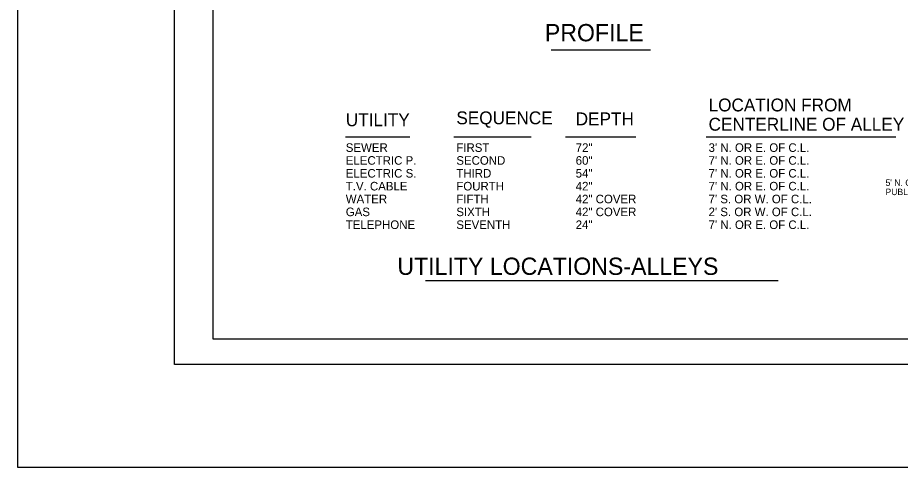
# Model space of a CAD drawing. Extents: x 524397 to 525117, y 3701341 to 3701821.
# Drawn here: x 524396.8 to 524603, y 3701341 to 3701445.9 of the extents above; entities that cross this region are included whole.
import ezdxf

# ---------------------------------------------------------------- set-up
doc = ezdxf.new("R2010")
doc.units = 0
for name, color, linetype in [('Level 1', 7, 'Continuous'), ('Level 9', 7, 'Continuous'), ('Pam batch print border', 7, 'Continuous')]:
    doc.layers.add(name, color=color, linetype=linetype)

msp = doc.modelspace()

# ---------------------------------------------------------------- linework, layer by layer
at = {"layer": 'Level 1'}
for p, q in [((524442.4, 3701790.98), (524442.4, 3701370.98)), ((524521.38, 3701438.43), (524544.58, 3701438.43)), ((524473.35, 3701418.16), (524488.42, 3701418.16)), ((524498.7, 3701418.16), (524516.74, 3701418.16)), ((524524.74, 3701418.16), (524541.18, 3701418.16)), ((524557.63, 3701418.16), (524601.94, 3701418.16)), ((524492.06, 3701384.56), (524574.43, 3701384.56)), ((524442.4, 3701370.98), (525097.4, 3701370.98))]:
    msp.add_line(p, q, dxfattribs=at)
at = {"layer": 'Level 9'}
msp.add_lwpolyline([(524396.79, 3701820.98), (525116.79, 3701820.98), (525116.79, 3701340.98), (524396.79, 3701340.98)], close=True, dxfattribs=at)
at = {"layer": 'Pam batch print border'}
msp.add_lwpolyline([(524433.4, 3701796.98), (525105.4, 3701796.98), (525105.4, 3701364.98), (524433.4, 3701364.98)], close=True, dxfattribs=at)
msp.add_lwpolyline([(524433.4, 3701796.98), (525105.4, 3701796.98), (525105.4, 3701364.98), (524433.4, 3701364.98)], close=True, dxfattribs=at)

# ---------------------------------------------------------------- texts
at = {"layer": 'Level 1'}
for s, height, p in [('PROFILE', 4.036, (524519.93, 3701440.42)), ('LOCATION FROM', 3, (524558.17, 3701424.06)), ('UTILITY', 3, (524473.43, 3701420.6)), ('SEQUENCE', 3, (524499.25, 3701421.05)), ('DEPTH', 3, (524527.13, 3701420.82)), ('CENTERLINE OF ALLEY', 3, (524558.17, 3701419.56)), ('SEWER', 2, (524473.43, 3701414.61)), ('FIRST', 2, (524499.25, 3701414.61)), ('72"', 2, (524527.13, 3701414.61)), ("3' N. OR E. OF C.L.", 2, (524558.17, 3701414.61)), ('ELECTRIC P.', 2, (524473.43, 3701411.61)), ('SECOND', 2, (524499.25, 3701411.61)), ('60"', 2, (524527.13, 3701411.61)), ("7' N. OR E. OF C.L.", 2, (524558.17, 3701411.61)), ('ELECTRIC S.', 2, (524473.43, 3701408.61)), ('THIRD', 2, (524499.25, 3701408.61)), ('54"', 2, (524527.13, 3701408.61)), ("7' N. OR E. OF C.L.", 2, (524558.17, 3701408.61)), ("5' N. OR E. OF C.L. IF NOT IN ", 1.5, (524599.5, 3701406.68)), ('T.V. CABLE', 2, (524473.43, 3701405.61)), ('FOURTH', 2, (524499.25, 3701405.61)), ('42"', 2, (524527.13, 3701405.61)), ("7' N. OR E. OF C.L.", 2, (524558.17, 3701405.61)), ('PUBLIC SERVICE DITCH', 1.5, (524599.5, 3701404.52)), ('WATER', 2, (524473.43, 3701402.61)), ('FIFTH', 2, (524499.25, 3701402.61)), ('42" COVER', 2, (524527.13, 3701402.61)), ("7' S. OR W. OF C.L.", 2, (524558.17, 3701402.61)), ('GAS', 2, (524473.43, 3701399.61)), ('SIXTH', 2, (524499.25, 3701399.61)), ('42" COVER', 2, (524527.13, 3701399.61)), ("2' S. OR W. OF C.L.", 2, (524558.17, 3701399.61)), ('TELEPHONE', 2, (524473.43, 3701396.61)), ('SEVENTH', 2, (524499.25, 3701396.61)), ('24"', 2, (524527.13, 3701396.61)), ("7' N. OR E. OF C.L.", 2, (524558.17, 3701396.61)), ('UTILITY LOCATIONS-ALLEYS', 4.0362, (524485.48, 3701385.9))]:
    msp.add_text(s, height=height, dxfattribs=at).set_placement(p)

doc.saveas('drawing.dxf')
